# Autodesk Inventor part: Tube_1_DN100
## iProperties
Shininess: 64.0
Length Units: 11269
Angle Units: 11279
Time Units: 11290
Mass Units: 11283
Length Display Precision: 3
Angle Display Precision: 2
Compacted: True
Part Number: Tube_1_DN100
Document SubType Name: Modeling
Created: 2008-04
Material: Par défaut
Designer: plup
Density: 0.0
Volumn: 0.0
Area: 0.0
PropertySet Name: Model Information
Control State: 0
Master: False
Checked Out: False
MATIERE_PIECE: X2CrNi 18-11
OBSERVATIONS: Lg.: .......
DESIGNATION: Tube 1
Author: plup
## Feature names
1. Extrusion1
